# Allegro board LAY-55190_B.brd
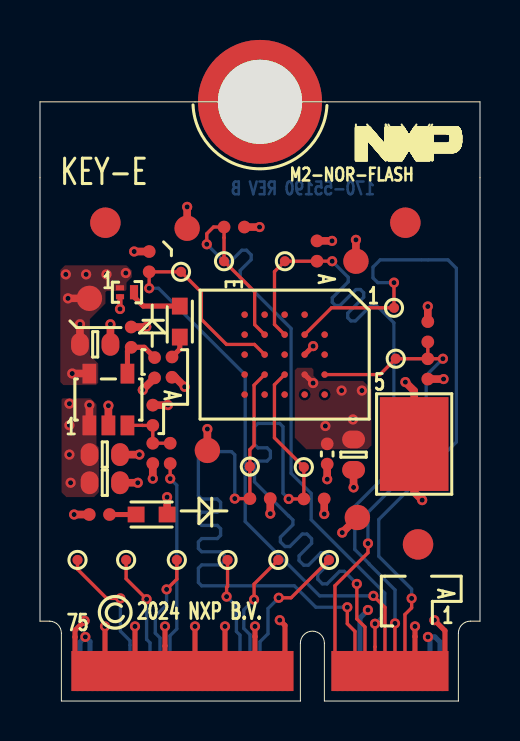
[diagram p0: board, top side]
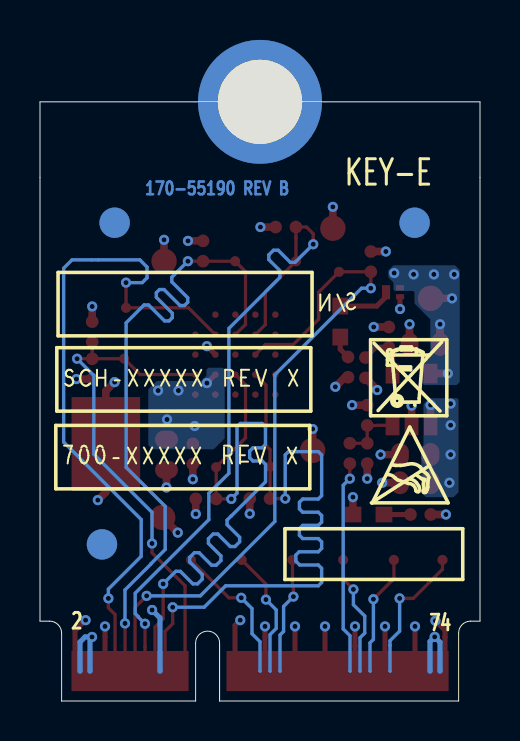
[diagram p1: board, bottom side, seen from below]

Outline 22 x 30 mm; copper layers: TOP, L2_GND_1, L3_GND_2, BOTTOM. Coordinates in mm from the lower left corner of the outline.
Outline path: 0,30 0,4 0.47,4 arc(0.89,3.82) 1.07,3.4 1.07,0 13.02,0 13.02,2.9 arc(13.62,3.5) 14.22,2.9 14.22,0 20.92,0 20.92,3.4 arc(21.1,3.82) 21.52,4 22,4 22,30 12.75,30 arc(11,28.25) 9.25,30 0,30

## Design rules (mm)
constraint set DEFAULT: min track width 0.165
net group MG1: nets DQ_0 DQ_1 DQ_2 DQ_3 SCLK SS_B

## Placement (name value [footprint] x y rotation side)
BH1  SMTSO-M2.5-5ET  [MH244-166T_202H]  11 30 0 top
C1  0.1uF  [CC0402_25]  14.36 12.37 270 top
C2  1uF  [CC0603_OV]  3.24 12.34 0 top
C3  1uF  [CC0603_OV]  2.76 17.86 0 top
C4  10uF  [CC0603_OV]  3.24 10.93 0 top
C5  4.7uF  [CC0603_OV]  15.68 12.34 270 top
D1  LED_GREEN  [LED_0603]  5.58 9.34 0 top
D2  LED_GREEN  [LED_0603]  6.99 19 90 top
J1  CONN_PCIE_67P  [CON_EDGE_67P_0P5_SM]  11 0.5 0 top
NOREF  -  []  1.07 0 0 top
NOREF#2  -  [unnamed#2]  18.27 23.95 0 top
NOREF#3  -  []  1.07 -0.08 0 top
NOREF#4  -  [unnamed#2]  18.9 7.84 0 top
NOREF#5  -  []  2 1.5 0 top
NOREF#6  -  []  12.5 1.5 0 top
NOREF#7  -  []  3.82 20.14 0 top
NOREF#8  -  []  20.95 3.59 0 top
NOREF#9  -  []  20.92 -0.08 90 top
NOREF#10  -  []  -192.34 -229.9 0 top
NOREF#11  -  []  199.27 -146.27 0 top
NOREF#12  -  []  20.92 0 90 top
NOREF#13  -  []  1.07 0 90 top
NOREF#14  -  []  3.95 -107.71 0 top
NOREF#15  -  []  1.07 0 0 top
NOREF#16  -  []  14.22 0 0 top
NOREF#17  -  []  0.86 7.27 0 top
NOREF#18  -  []  -380.86 -331.86 0 top
NOREF#19  -  []  20.92 -0.08 90 top
NOREF#20  -  []  -356.25 188.39 0 top
NOREF#21  -  [unnamed#2]  3.27 23.95 0 top
NOREF#22  -  []  1.07 0 0 top
NOREF#23  -  []  2.5 1.5 0 top
NOREF#24  -  []  0 30 0 top
NOREF#25  -  []  13.02 0 0 top
NOREF#26  -  []  18.08 0.48 0 top
NOREF#27  -  []  4 20.24 90 top
NOREF#28  -  []  4 20.24 0 top
NOREF#29  -  []  20.92 0 90 top
NOREF#30  -  []  15 1.5 0 top
NOREF#31  -  []  3.82 20.14 90 top
NOREF#32  -  [unnamed#2]  18.9 7.84 180 bottom
NOREF#33  -  [unnamed#2]  18.27 23.95 180 bottom
NOREF#34  -  [unnamed#2]  3.27 23.95 180 bottom
Q1  PMZB550UNE  [DFN10106B]  4.35 20.47 0 top
R1  10.0K  [RC0402_25]  13.85 22.53 270 top
R2  390  [RC0402_25]  2.97 9.34 0 top
R3  150  [RC0402_25]  6.6 16.72 270 top
R4  10.0K  [RC0402_25]  19.39 16.63 90 top
R5  10.0K  [RC0402_25]  19.39 18.49 90 top
R6  10.0K  [RC0402_25]  5.64 14.31 270 top
R7  10.0K  [RC0402_25]  5.64 12.4 270 top
R8  1.0K  [RC0402_25]  6.51 12.4 90 top
R9  10.0K  [RC0402_25]  13.7 10.12 180 top
R10  10.0K  [RC0402_25]  5.46 22 270 top
R11  15K  [RC0402_25]  4.56 18.22 270 top
R12  12.0K  [RC0402_25]  5.73 16.69 270 top
R13  10.0K  [RC0402_25]  9.71 23.73 180 top
R14  10.0K  [RC0402_25]  11 10.14 180 top
TP1  -  [TPAD_020]  7.05 21.49 270 top
TP2  -  [TPAD_020]  9.2 22.02 0 top
TP3  -  [TPAD_020]  13.19 11.71 270 top
TP4  -  [TPAD_020]  10.49 11.74 0 top
TP5  -  [TPAD_020]  17.7 19.69 0 top
TP6  -  [TPAD_020]  12.25 22.02 0 top
TP7  -  [TPAD_020]  17.79 17.14 0 top
TP8  -  [TPAD_050]  2.47 20.16 0 top
TP9  -  [TPAD_020]  14.45 7.06 0 top
TP10  -  [TPAD_020]  11.91 7.06 0 top
TP11  -  [TPAD_020]  9.38 7.06 0 top
TP12  -  [TPAD_020]  6.84 7.06 0 top
TP13  -  [TPAD_020]  4.31 7.06 0 top
TP14  -  [TPAD_020]  1.88 7.06 0 top
TP15  -  [TPAD_050]  15.8 22.02 0 top
TP16  -  [TPAD_050]  8.37 12.55 0 top
TP17  -  [TPAD_050]  15.87 9.19 0 top
TP18  -  [TPAD_050]  7.36 23.67 270 top
TP19  TESTLOOP  [TEST_PIN_TP107]  18.71 12.87 270 top
U1  MT25QU512ABB8E12-0AAT  [PBGA24_1_6X8MM]  12.23 17.34 270 top
U2  NCP161ASN180T1G  [SOT-23-5]  3.42 15.1 0 top

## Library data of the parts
BH1 = MOUNT_HOLE
C1-C5 = CAP_NP
D1 D2 = LED
J1 = PCIEXPRESS_CONN67P_A
Q1 = NMOS_NX3008NBK
R1-R14 = RES
TP1-TP19 = TestLoop
U1 = MT25QU512ABA8E12-BGA24_A
U2 = NCP161ASN180T1G

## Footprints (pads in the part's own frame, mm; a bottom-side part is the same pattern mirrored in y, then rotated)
CC0402_25
  round 0.635 smd: 1(-0.508,0) 2(0.508,0)
CC0603_OV
  oval 0.889x1.143 smd: 1(-0.762,0) 2(0.762,0)
CON_EDGE_67P_0P5_SM
  rect 0.356x2.007 smd: 1(9.25,1) 2(9,1) 3(8.75,1) 4(8.5,1) 5(8.25,1) 6(8,1) 7(7.75,1) 8(7.5,1) 9(7.25,1) 10(7,1) 11(6.75,1) 12(6.5,1) 13(6.25,1) 14(6,1) 15(5.75,1) 16(5.5,1) 17(5.25,1) 18(5,1) 19(4.75,1) 20(4.5,1) 21(4.25,1) 22(4,1) 23(3.75,1) 32(1.5,1) 33(1.25,1) 34(1,1) 35(0.75,1) 36(0.5,1) 37(0.25,1) 38(0,1) 39(-0.25,1) 40(-0.5,1) 41(-0.75,1) 42(-1,1) 43(-1.25,1) 44(-1.5,1) 45(-1.75,1) 46(-2,1) 47(-2.25,1) 48(-2.5,1) 49(-2.75,1) 50(-3,1) 51(-3.25,1) 52(-3.5,1) 53(-3.75,1) 54(-4,1) 55(-4.25,1) 56(-4.5,1) 57(-4.75,1) 58(-5,1) 59(-5.25,1) 60(-5.5,1) 61(-5.75,1) 62(-6,1) 63(-6.25,1) 64(-6.5,1) 65(-6.75,1) 66(-7,1) 67(-7.25,1) 68(-7.5,1) 69(-7.75,1) 70(-8,1) 71(-8.25,1) 72(-8.5,1) 73(-8.75,1) 74(-9,1) 75(-9.25,1)
DFN10106B
  rect 0.406x0.254 smd: 1(-0.35,0.225) 2(-0.35,-0.225)
  rect 0.406x0.711 smd: 3(0.35,0)
LED_0603
  rect 0.838x0.787 smd: A(-0.775,0) C(0.775,0)
MH244-166T_202H
  round 6.198 hole 4.216: 1(0,0)
PBGA24_1_6X8MM
  round 0.33 smd: A2(-1,2) A3(0,2) A4(1,2) A5(2,2) B1(-2,1) B2(-1,1) B3(0,1) B4(1,1) B5(2,1) C1(-2,0) C2(-1,0) C3(0,0) C4(1,0) C5(2,0) D1(-2,-1) D2(-1,-1) D3(0,-1) D4(1,-1) D5(2,-1) E1(-2,-2) E2(-1,-2) E3(0,-2) E4(1,-2) E5(2,-2)
RC0402_25
  round 0.635 smd: 1(-0.508,0) 2(0.508,0)
SOT-23-5
  rect 0.686x0.991 smd: 1(-0.953,-1.295) 2(0,-1.295) 3(0.953,-1.295) 4(0.953,1.295) 5(-0.953,1.295)
TEST_PIN_TP107
  rect 4.699x3.429 smd: 1(0,0)
TPAD_020
  round 0.508 smd: 1(0,0)
TPAD_050
  round 1.27 smd: 1(0,0)
unnamed#2
  round 1.52 smd: (0,0)

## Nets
1.8V: C1.1 C3.1 C5.1 Q1.1 R1.1 R4.1 R9.1 R10.1 R11.1 R13.1 R14.1 TP8.1(PIN1) U1.B4 U2.5(OUT)
3.3V: C2.1 C4.1 J1.2 J1.4 J1.72 J1.74 R2.1 R3.2 R6.1 U2.1
GND: BH1.1 C1.2 C2.2 C3.2 C4.2 C5.2 D1.C(CATHODE) J1.1 J1.7 J1.18 J1.33 J1.39 J1.45 J1.51 J1.57 J1.63 J1.69 J1.75 Q1.2(SOURCE) R5.2 R7.2 R12.2 TP15.1(PIN1) TP16.1(PIN1) TP17.1(PIN1) TP18.1(PIN1) TP19.1(PIN1) U1.B3 U2.2
DQ_0: J1.13 R10.2 TP1.1(PIN1) U1.D3
DQ_1: J1.15 R13.2 TP2.1(PIN1) U1.D2
DQ_2: J1.17 R9.2 TP3.1(PIN1) U1.C4(W\/DQ2)
DQ_3: J1.19 R14.2 TP4.1(PIN1) U1.D4
EN_LDO: J1.56(W_DISABLE#1) R8.1
EN_LDO_R: R6.2 R7.1 R8.2 U2.3
RESET_B: J1.23 R4.2 R5.1 TP7.1(PIN1) U1.A4
SCLK: J1.9 TP5.1(PIN1) U1.B2
SS_B: J1.11 R1.2 TP6.1(PIN1) U1.C2
N30624074: J1.38 TP9.1(PIN1)
N30624085: J1.40 TP10.1(PIN1)
N30624096: J1.42 TP11.1(PIN1)
N30624128: J1.58 TP12.1(PIN1)
N30624137: J1.60 TP13.1(PIN1)
N30624146: J1.64 TP14.1(PIN1)
N30625327: D2.C(CATHODE) Q1.3
N30627604: D2.A R3.1
N30628082: R11.2 R12.1 U2.4
N306252630: D1.A R2.2

Pads without a net: J1 3 5 6 8 10 12 14 16 20 21 22 32 34 35 36 37 41 43 44 46 47 48 49 50 52 53 54 55 59 61 62 65 66 67 68 70 71 73; U1 A2 A3 A5 B1 B5 C1 C3 C5 D1 D5 E1 E2 E3 E4 E5

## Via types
v1: diameter 0.508, hole 0.254, TOP to BOTTOM, 79 vias

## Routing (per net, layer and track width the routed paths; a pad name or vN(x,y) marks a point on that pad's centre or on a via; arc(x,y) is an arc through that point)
1.8V: length 8.9
  TOP w0.254: U1.B4 v1(13.66,15.92)
  TOP w0.381: C3.1 v1(2,18.86) ; R9.1 14.21,10.12 v1(14.21,9.36) ; 2.47,16.4 v1(1.61,16.4) ; R10.1 v1(4.71,22.51) ; v1(11.51,9.38) 11.51,10.14 R14.1 ; TP8.1 v1(1.4,20.16) ; v1(5.31,18.73) 5.31,18.73 R11.1 ; R4.1 v1(20.18,16.12) ; v1(14.6,23.04) R1.1 ; R13.1 v1(10.98,23.73)
  vias: v1(1.29,21.36) v1(2.31,21.36) v1(3.32,21.36) v1(4.29,21.43) v1(14.27,13.77) v1(15.08,15.55) v1(15.65,14.1) v1(16.1,15.55)
3.3V: length 10.9
  TOP w0.381: 2.47,13.8 v1(2.47,14.82) ; R6.1 6.39,14.82 v1(6.39,14.82) ; v1(7.23,15.73) 6.76,16.21 R3.2 ; R2.1 v1(1.7,9.34)
  BOTTOM w0.254: J1.2 20,1.51 20,2.96 19.75,3.21 v1(19.4,3.21) 19.5,3.11 19.5,1.51 J1.4 ; J1.74 2,1.51 2,2.95 v1(2.27,3.21) 2.5,2.98 2.5,1.51 J1.72
  vias: v1(1.47,14.89) v1(1.47,13.81) v1(1.47,12.34) v1(1.53,10.93)
GND: length 47.5
  TOP w0.254: J1.39 10.75,3.23 10.75,3.23 v1(10.75,3.74) ; J1.7 18.75,3.23 18.75,3.23 v1(18.75,3.74) ; J1.75 1.75,1.51 1.75,3.21 1.75,3.54 v1(2.23,4.02) ; J1.33 12.25,3.79 v1(11.99,4.05) ; v1(3.25,3.74) 3.25,1.51 J1.69 ; J1.57 6.25,2.76 6.25,2.76 v1(6.25,3.74) ; J1.63 4.75,1.51 v1(4.75,3.74) ; J1.51 7.75,1.51 v1(7.75,3.74) ; Q1.2 v1(4,19.63) ; J1.1 20.25,3.52 v1(19.72,4.05) ; J1.45 9.25,1.51 v1(9.25,3.74) ; U1.B3 v1(13.66,17.77)
  TOP w0.381: U2.2 v1(3.42,14.79) ; R5.2 v1(19.39,19.76) ; C3.2 v1(3.52,18.86) ; v1(18.27,15.97) 18.71,15.53 TP19.1 18.71,10.46 v1(19.11,10.06) ; TP15.1 v1(15.8,23.09) ; R7.2 v1(5.64,11.13) ; TP16.1 v1(8.37,13.62) ; C4.2 v1(4.89,10.93) ; R12.2 5.73,16.18 5.14,15.59 v1(5.14,15.57) ; C2.2 v1(4.97,12.34) ; v1(15.11,8.43) TP17.1 ; C5.2 v1(15.68,10.7) ; C1.2 v1(14.36,11.1) ; D1.C v1(6.35,10.21) ; TP18.1 v1(7.36,24.74)
  BOTTOM w0.254: J1.18 16,1.51 16,4.16 v1(16.4,4.56)
DQ_0: length 35
  TOP w0.165: U1.D3 10.72,17.85 9.32,17.85 8.07,19.11 8.07,20.47 TP1.1 5.46,21.49 R10.2 v1(5.46,20.67) ; J1.13 17.25,4.69 v1(16.67,5.27)
  BOTTOM w0.165: v1(16.67,5.27) 13.98,5.27 10.26,8.99 10.26,16.33 5.92,20.67 v1(5.46,20.67)
DQ_1: length 35
  TOP w0.165: v1(8.34,22.87) 8.34,23.4 8.67,23.73 R13.2 9.2,23.2 9.2,23.2 TP2.1 10.73,20.49 10.73,18.84 U1.D2 ; v1(16.75,3.87) 16.75,2.72 16.75,2.72 J1.15
  BOTTOM w0.165: v1(16.75,3.87) 17.08,4.2 17.08,4.21 17.24,4.38 17.24,5.4 13.56,9.08 13.56,10.4 12.55,11.4 12.55,18.65 10.01,21.2 10.01,21.55 10.56,22.1 10.56,22.34 10.33,22.57 10.09,22.57 9.48,21.96 9.25,21.96 v1(8.34,22.87)
DQ_2: length 34.9
  TOP w0.165: J1.17 16.25,3.71 15.84,4.11 v1(15.84,5.86) ; v1(12.44,10.12) R9.2 13.19,10.12 TP3.1 11.72,13.18 11.72,15.84 U1.C4
  BOTTOM w0.165: v1(12.44,10.12) 12.15,10.41 12.15,13.73 11.98,13.9 10.89,13.9 10.73,13.73 10.73,12.84 10.89,12.68 11.35,12.68 11.52,12.51 11.52,12.18 11.35,12.02 10.89,12.02 10.72,11.85 10.72,10.97 12.43,9.27 12.44,9.27 12.64,9.06 12.64,8.83 12.02,8.2 12.02,7.97 12.25,7.74 12.49,7.74 13.11,8.36 13.35,8.36 13.58,8.13 13.58,7.89 12.95,7.27 12.95,7.04 13.19,6.8 13.42,6.8 14.05,7.43 14.28,7.43 14.51,7.19 14.51,6.96 13.89,6.34 13.89,6.1 14.12,5.87 14.35,5.87 14.98,6.49 15.21,6.49 v1(15.84,5.86)
DQ_3: length 35
  TOP w0.165: v1(9.74,10.14) R14.2 10.49,10.14 TP4.1 10.49,12.59 10.7,12.8 10.7,15.82 U1.D4 ; J1.19 15.75,3.49 15.37,3.87 v1(15.37,4.7)
  BOTTOM w0.165: v1(15.37,4.7) 13.79,4.7 12.72,5.77 8.08,5.77 7.92,5.93 7.92,6.65 8.08,6.81 9.01,6.81 9.21,7.01 9.21,7.31 9.04,7.47 8.08,7.47 7.92,7.64 7.92,7.97 8.08,8.13 8.86,8.13 9.03,8.3 9.03,8.63 8.86,8.79 8.08,8.79 7.92,8.96 7.92,9.29 8.08,9.46 8.86,9.46 9.03,9.62 9.03,9.95 8.86,10.12 8.08,10.12 7.92,10.28 7.92,12.32 8.08,12.49 9.57,12.49 9.74,12.32 v1(9.74,10.14)
EN_LDO: length 10.7
  TOP w0.165: R8.1 v1(6.51,11.13)
  BOTTOM w0.165: v1(6.51,11.13) 6.84,10.8 6.84,3.61 6.5,3.27 6.5,1.51 J1.56
EN_LDO_R: length 3
  TOP w0.165: U2.3 5.11,13.8 5.11,13.8 R6.2 R7.1 R8.2
RESET_B: length 25
  TOP w0.165: R5.1 R4.2 ; R4.2 19.39,17.14 v1(20.15,17.14) ; R4.2 19.39,17.14 TP7.1 16.99,16.34 U1.A4 ; v1(16.4,7.89) 16.4,7.43 14.75,5.77 J1.23
  BOTTOM w0.165: v1(16.4,7.89) 16.4,9.45 19.31,12.36 19.31,16.3 v1(20.15,17.14)
SCLK: length 35.1
  TOP w0.165: U1.B2 14.58,19.69 TP5.1 v1(17.7,20.95) ; J1.9 18.25,4.33 18.58,4.67 v1(18.58,5.14)
  BOTTOM w0.165: v1(17.7,20.95) 16.89,20.95 16.65,21.19 16.65,21.73 17.01,22.09 19.08,22.09 19.42,22.09 20.4,22.09 20.82,21.67 20.82,12.97 16.94,9.09 16.94,7.25 18.58,5.6 v1(18.58,5.14)
SS_B: length 35
  TOP w0.165: U1.C2 11.72,18.85 11.72,21.5 TP6.1 13.85,22.02 R1.2 14.61,22.02 v1(14.61,22.02) ; J1.11 17.75,3.88 v1(17.75,3.89)
  BOTTOM w0.165: v1(14.61,22.02) 15.41,21.22 15.41,20.99 14.61,20.19 14.61,19.96 14.77,19.8 15,19.8 15.8,20.6 16.02,20.6 16.18,20.44 16.18,20.22 15.39,19.42 15.39,19.19 15.55,19.03 15.77,19.03 16.57,19.83 16.8,19.83 17.69,18.93 17.69,11.7 15.74,9.75 15.74,7.59 16.46,6.87 16.46,6.85 17.75,5.56 v1(17.75,3.89)
N30624074: length 7.4
  TOP w0.165: v1(11.94,5.17) 12.56,5.17 TP9.1
  BOTTOM w0.165: J1.38 11,1.51 11,2.97 11.4,3.37 11.4,4.63 v1(11.94,5.17)
N30624085: length 6.4
  TOP w0.165: v1(10.7,5.08) 10.7,5.85 TP10.1
  BOTTOM w0.165: v1(10.7,5.08) 10.19,4.57 10.19,3.64 10.5,3.33 10.5,1.51 J1.40
N30624096: length 5.9
  TOP w0.165: v1(9.33,5.23) 9.33,5.7 9.38,5.75 TP11.1
  BOTTOM w0.165: v1(9.33,5.23) 9.82,4.74 9.82,3.48 10,3.31 10,1.51 J1.42
N30624128: length 6.1
  TOP w0.165: TP12.1 6.84,6.1 v1(6.33,5.59)
  BOTTOM w0.165: v1(6.33,5.59) 6.33,4.82 5.76,4.26 5.76,3.4 6,3.17 6,1.51 J1.58
N30624137: length 6.1
  TOP w0.165: v1(5.33,5.1) 4.31,6.12 TP13.1
  BOTTOM w0.165: J1.60 5.5,1.51 5.5,2.92 5.33,3.09 v1(5.33,5.1)
N30624146: length 7.1
  TOP w0.165: v1(4.02,5.14) 3.33,5.14 1.88,6.6 TP14.1
  BOTTOM w0.165: v1(4.02,5.14) 4.02,3.5 4.5,3.02 4.5,2.79 4.5,2.79 4.5,1.51 J1.64
N30625327: length 2.7
  TOP w0.254: D2.C 5.16,19.77 4.7,20.24 Q1.3
N30627604: length 1.2
  TOP w0.254: R3.1 6.99,17.62 D2.A
N30628082: length 2.8
  TOP w0.254: U2.4 4.37,17.52 R11.2 5.22,17.71 R12.1
N306252630: length 1.3
  TOP w0.254: D1.A R2.2

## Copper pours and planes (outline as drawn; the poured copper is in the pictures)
1.8V on TOP: 12.74,16.57 12.74,13.18 13.31,12.61 16.38,12.61 16.58,12.81 16.58,15.61 16.16,16.03 13.94,16.03 13.67,16.3 13.67,16.6 13.58,16.69 12.86,16.69
1.8V on TOP, BOTTOM: 1.26,21.82 4.32,21.82 4.59,21.55 4.59,21.22 4.32,20.95 4.32,20.59 4.26,20.53 3.33,20.53 3.27,20.47 3.27,19.9 2.49,19.12 2.49,17.32 2.91,16.9 2.91,15.94 2.79,15.82 1.17,15.82 1.02,15.97 1.02,21.58
1.8V on BOTTOM: 12.74,16.57 12.74,13.18 13.31,12.61 16.38,12.61 16.58,12.81 16.58,15.61 16.16,16.03 13.94,16.03 13.67,16.3 13.67,16.6 13.58,16.69 12.86,16.69
1.8V on L2_GND_1: 1,25.2 20.98,25.2 20.98,9.78 20.33,9.12 9.62,9.12 9.05,9.69 9.05,16.62 8.12,17.55 1.28,17.55 1,17.83
3.3V on TOP, BOTTOM: 1.14,15.16 2.52,15.16 2.82,14.86 2.82,12.82 2.94,12.7 2.94,10.45 2.7,10.21 1.32,10.21 1.08,10.45 1.08,15.1
3.3V on L2_GND_1: 19.87,7.29 19.87,1.13 19.75,1.01 15.86,1.01 15.56,1.31 15.56,3.81 14.49,4.88 12.55,4.88 11.87,4.2 11.87,2.79 11.8,2.72 2.07,2.72 2.07,2.72 2.07,3.4 1.78,4.33 1,4.91 1,16.53 1.45,16.98 7.7,16.98 8.45,16.23 8.45,8.94 8.99,8.4 18.77,8.4
GND on L3_GND_2: 21,29 21,4.91 20.22,4.33 19.92,3.4 19.92,1 15.22,1 15.22,2.9 13.62,4.5 12.02,2.9 12.02,1 2.07,1 2.07,3.4 1.78,4.33 1,4.91 1,29 7.29,29 7.29,30 14.85,30 14.85,29

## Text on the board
BOTTOM: 170-55190 REV B | 7 OF 10 | L4_SS
Board Geometry/Soldermask Bottom: 10 OF 10 | SECONDARY SOLDERMASK
Ref Des/Silkscreen Bottom: KEY-E | 9 OF 10 | SECONDARY SILKSCREEN
User.Comments: 1 OF 1 | TEST PROBE | 1/1 | 1 | 2
TOP: 4 OF 10 | L1_PS
Board Geometry/Soldermask Top: 3 OF 10 | PRIMARY SOLDERMASK
Ref Des/Silkscreen Top: M2-NOR-FLASH | 2024 NXP B.V. | A | KEY-E | 2 OF 10 | PRIMARY SILKSCREEN
L2_GND_1: 5 OF 10 | L2_GND_1
L3_GND_2: 6 OF 10 | L3_GND_2
XSECTION_CHART: *  SURFACE - AIR 0 MIL | *  DIELECTRIC - LPI 0.75 MIL | L1 TOP CONDUCTOR - 1OZ_COPPER 0.55 MIL | *  DIELECTRIC - IT-180A 4.31 MIL | L2 L2_GND_1 PLANE - 1OZ_COPPER 1.4 MIL | *  DIELECTRIC - IT-180A 16.41 MIL | L3 L3_GND_2 PLANE - COPPER 1.4 MIL | L4 BOTTOM CONDUCTOR - 1OZ_COPPER 0.55 MIL | DESIGN CROSS SECTION CHART | ___________________________ | TOTAL THICKNESS 30.43 MIL | 1-4
DIMENSION: 0.013" | SCALE: NONE | 24 | B. THE PCI CARD CONNECTOR FINGERS SHALL BE PLATED WITH A MINIMUM | 7 | 30 MICRO INCHES OF HARD GOLD OVER 100-200 MICRO INCHES OF NICKEL BOTH SIDES OF THE BOARD. | B | 19 | 16 | DETAIL | LAYER STACKUP | PRIMARY DATUM | GRID ORIGIN | A
PASTEMASK_TOP: 1 OF 10 | PASTEMASK TOP
User.5: 8 OF 10 | SECONDARY PASTEMASK
User.11: 30,00 | 22,00 | R2,75 | R1,75 | 0,80
User.13: 05-02-24
User.16: 22. THIS FAB_VIAFILL.ART SHOWS LOCATIONS OF VIA-IN-PAD TO BE FILLED. | 1/1 | 2
User.17: 24.
User.19: 05-02-24 | K.N. | L.C. | A.U. | B | PRODUCTION RELEASE
User.35: TOP TO LAYER X | BACK DRILL REFERENCE | BOTTOM TO LAYER X | LAYER X | MUST CUT LAYER | LAYER X+1 | MUST NOT CUT LAYER | LAYER X-1
User.38: FIGURE | FINISHED_SIZE | 10.0 | 166.0 | DRILL CHART: TOP to BOTTOM | ALL UNITS ARE IN MILS | TOLERANCE_DRILL | +0.0/-10.0 | +3.0/-3.0 | PLATED | QTY | 79 | 1 | 80 | TOTAL HOLES:
